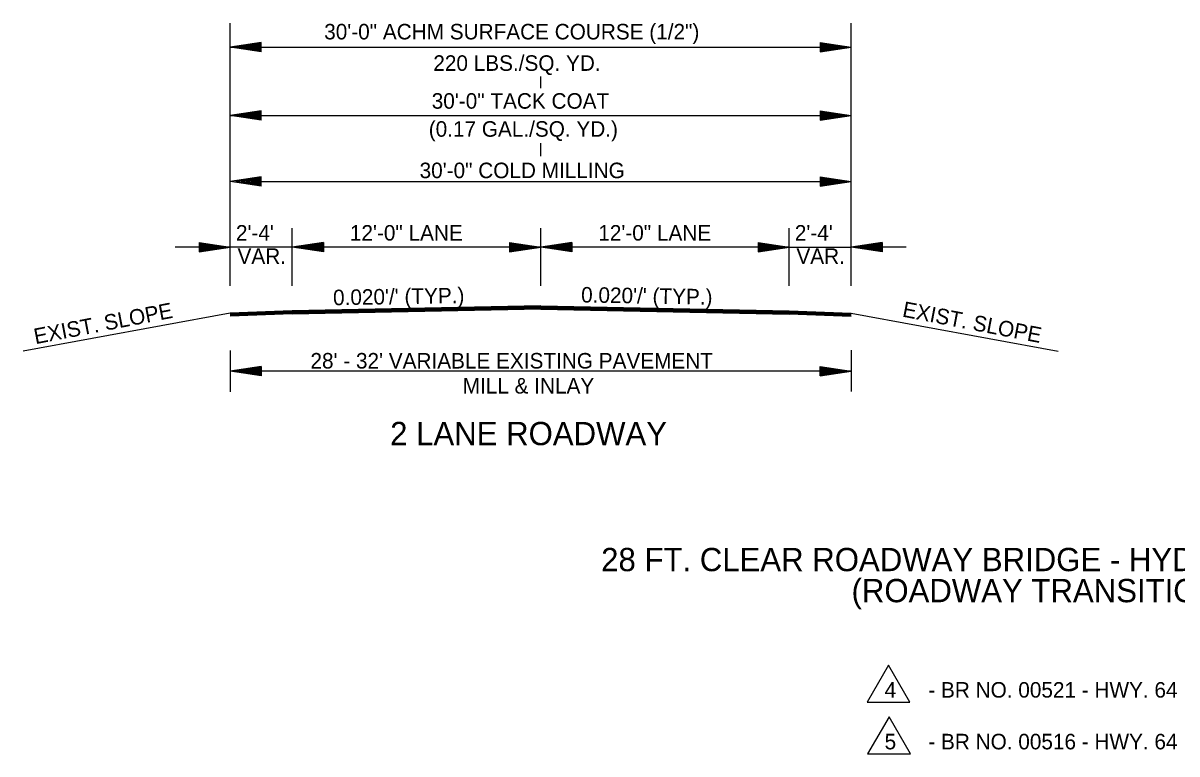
# Model space of a CAD drawing. Extents: x 549600 to 1930787, y -1955432 to 596640.
# Drawn here: x 551122 to 551679, y -1946099 to -1945746 of the extents above; entities that cross this region are included whole.
import ezdxf

# ---------------------------------------------------------------- set-up
doc = ezdxf.new("R2010")
doc.units = 0
doc.layers.add('R_Border', color=7, linetype='Continuous')
doc.layers.add('S_AREA_CALC', color=7, linetype='Continuous')

msp = doc.modelspace()

# ---------------------------------------------------------------- linework, layer by layer
at = {"layer": 'R_Border'}
for p, q in [((551529.77, -1946073.9), (551550.43, -1946073.9)), ((551529.96, -1946098.9), (551550.62, -1946098.9))]:
    msp.add_line(p, q, dxfattribs=at)
for points in [[(551550.43, -1946073.9), (551540.1, -1946056), (551529.77, -1946073.9)], [(551550.62, -1946098.9), (551540.29, -1946081), (551529.96, -1946098.9)]]:
    msp.add_lwpolyline(points, dxfattribs=at)
at = {"layer": 'S_AREA_CALC'}
for p, q in [((551222.02, -1945872.78), (551222.02, -1945745.75)), ((551522.02, -1945872.78), (551522.02, -1945745.75)), ((551237.02, -1945755.17), (551222.02, -1945757.42)), ((551237.02, -1945755.55), (551224.52, -1945757.42)), ((551237.02, -1945755.93), (551227.1, -1945757.42)), ((551237.02, -1945759.67), (551237.02, -1945755.17)), ((551507.02, -1945755.17), (551522.02, -1945757.42)), ((551507.02, -1945755.17), (551507.02, -1945759.67)), ((551507.02, -1945755.55), (551519.51, -1945757.42)), ((551507.02, -1945755.93), (551516.93, -1945757.42)), ((551222.02, -1945757.42), (551522.02, -1945757.42)), ((551237.02, -1945759.67), (551222.02, -1945757.42)), ((551237.02, -1945759.3), (551224.52, -1945757.42)), ((551237.02, -1945758.91), (551227.1, -1945757.42)), ((551237.02, -1945756.3), (551229.6, -1945757.42)), ((551237.02, -1945758.54), (551229.6, -1945757.42)), ((551237.02, -1945756.69), (551232.14, -1945757.42)), ((551237.02, -1945758.15), (551232.14, -1945757.42)), ((551237.02, -1945757.07), (551234.65, -1945757.42)), ((551237.02, -1945757.77), (551234.65, -1945757.42)), ((551507.02, -1945756.3), (551514.44, -1945757.42)), ((551507.02, -1945756.69), (551511.89, -1945757.42)), ((551507.02, -1945757.07), (551509.39, -1945757.42)), ((551507.02, -1945759.67), (551522.02, -1945757.42)), ((551507.02, -1945758.16), (551511.89, -1945757.42)), ((551507.02, -1945758.91), (551516.93, -1945757.42)), ((551507.02, -1945759.3), (551519.51, -1945757.42)), ((551507.02, -1945758.54), (551514.44, -1945757.42)), ((551507.02, -1945757.77), (551509.39, -1945757.42)), ((551372.02, -1945777.16), (551372.02, -1945771.63)), ((551237.02, -1945788.14), (551222.02, -1945790.39)), ((551237.02, -1945788.51), (551224.52, -1945790.39)), ((551237.02, -1945788.89), (551227.1, -1945790.39)), ((551237.02, -1945789.27), (551229.6, -1945790.39)), ((551237.02, -1945789.65), (551232.14, -1945790.39)), ((551237.02, -1945792.64), (551237.02, -1945788.14)), ((551507.02, -1945788.14), (551522.02, -1945790.39)), ((551507.02, -1945788.14), (551507.02, -1945792.64)), ((551507.02, -1945788.51), (551519.51, -1945790.39)), ((551507.02, -1945788.89), (551516.93, -1945790.39)), ((551507.02, -1945789.27), (551514.44, -1945790.39)), ((551507.02, -1945789.66), (551511.89, -1945790.39)), ((551222.02, -1945790.39), (551522.02, -1945790.39)), ((551237.02, -1945792.64), (551222.02, -1945790.39)), ((551237.02, -1945792.26), (551224.52, -1945790.39)), ((551237.02, -1945791.88), (551227.1, -1945790.39)), ((551237.02, -1945791.5), (551229.6, -1945790.39)), ((551237.02, -1945791.11), (551232.14, -1945790.39)), ((551237.02, -1945790.03), (551234.65, -1945790.39)), ((551237.02, -1945790.74), (551234.65, -1945790.39)), ((551507.02, -1945790.03), (551509.39, -1945790.39)), ((551507.02, -1945792.64), (551522.02, -1945790.39)), ((551507.02, -1945791.12), (551511.89, -1945790.39)), ((551507.02, -1945791.88), (551516.93, -1945790.39)), ((551507.02, -1945792.26), (551519.51, -1945790.39)), ((551507.02, -1945791.5), (551514.44, -1945790.39)), ((551507.02, -1945790.74), (551509.39, -1945790.39)), ((551372.02, -1945810.13), (551372.02, -1945803.71)), ((551237.02, -1945820.11), (551222.02, -1945822.36)), ((551237.02, -1945824.61), (551222.02, -1945822.36)), ((551237.02, -1945820.49), (551224.52, -1945822.36)), ((551237.02, -1945824.24), (551224.52, -1945822.36)), ((551237.02, -1945820.87), (551227.1, -1945822.36)), ((551237.02, -1945823.85), (551227.1, -1945822.36)), ((551237.02, -1945821.24), (551229.6, -1945822.36)), ((551237.02, -1945823.48), (551229.6, -1945822.36)), ((551232.02, -1945822.36), (551522.02, -1945822.36)), ((551237.02, -1945821.63), (551232.14, -1945822.36)), ((551237.02, -1945823.09), (551232.14, -1945822.36)), ((551237.02, -1945822.01), (551234.65, -1945822.36)), ((551237.02, -1945822.71), (551234.65, -1945822.36)), ((551237.02, -1945824.61), (551237.02, -1945820.11)), ((551507.02, -1945820.11), (551522.02, -1945822.36)), ((551507.02, -1945820.11), (551507.02, -1945824.61)), ((551507.02, -1945820.49), (551519.51, -1945822.36)), ((551507.02, -1945820.87), (551516.93, -1945822.36)), ((551507.02, -1945821.24), (551514.44, -1945822.36)), ((551507.02, -1945821.63), (551511.89, -1945822.36)), ((551507.02, -1945822.01), (551509.39, -1945822.36)), ((551507.02, -1945824.61), (551522.02, -1945822.36)), ((551507.02, -1945823.1), (551511.89, -1945822.36)), ((551507.02, -1945823.85), (551516.93, -1945822.36)), ((551507.02, -1945824.24), (551519.51, -1945822.36)), ((551507.02, -1945823.48), (551514.44, -1945822.36)), ((551507.02, -1945822.71), (551509.39, -1945822.36)), ((551252.02, -1945872.78), (551252.02, -1945844.83)), ((551372.02, -1945872.78), (551372.02, -1945844.83)), ((551492.02, -1945872.78), (551492.02, -1945844.83)), ((551222.02, -1945854.02), (551195.5, -1945854.02)), ((551207.02, -1945851.77), (551222.02, -1945854.02)), ((551207.02, -1945851.77), (551207.02, -1945856.27)), ((551207.02, -1945852.15), (551219.51, -1945854.02)), ((551207.02, -1945852.53), (551216.93, -1945854.02)), ((551207.02, -1945852.9), (551214.44, -1945854.02)), ((551207.02, -1945853.29), (551211.89, -1945854.02)), ((551207.02, -1945853.67), (551209.39, -1945854.02)), ((551207.02, -1945856.27), (551222.02, -1945854.02)), ((551207.02, -1945854.76), (551211.89, -1945854.02)), ((551207.02, -1945855.51), (551216.93, -1945854.02)), ((551207.02, -1945855.9), (551219.51, -1945854.02)), ((551207.02, -1945855.14), (551214.44, -1945854.02)), ((551207.02, -1945854.37), (551209.39, -1945854.02)), ((551252.02, -1945854.02), (551222.02, -1945854.02)), ((551267.02, -1945851.77), (551252.02, -1945854.02)), ((551372.02, -1945854.02), (551252.02, -1945854.02)), ((551267.02, -1945856.27), (551252.02, -1945854.02)), ((551267.02, -1945852.15), (551254.52, -1945854.02)), ((551267.02, -1945855.9), (551254.52, -1945854.02)), ((551267.02, -1945852.53), (551257.1, -1945854.02)), ((551267.02, -1945855.51), (551257.1, -1945854.02)), ((551267.02, -1945852.9), (551259.6, -1945854.02)), ((551267.02, -1945855.14), (551259.6, -1945854.02)), ((551267.02, -1945853.29), (551262.14, -1945854.02)), ((551267.02, -1945854.76), (551262.14, -1945854.02)), ((551267.02, -1945853.67), (551264.65, -1945854.02)), ((551267.02, -1945854.37), (551264.65, -1945854.02)), ((551267.02, -1945851.77), (551267.02, -1945856.27)), ((551357.02, -1945851.77), (551372.02, -1945854.02)), ((551357.02, -1945851.77), (551357.02, -1945856.27)), ((551357.02, -1945852.15), (551369.51, -1945854.02)), ((551357.02, -1945852.53), (551366.93, -1945854.02)), ((551357.02, -1945852.9), (551364.44, -1945854.02)), ((551357.02, -1945853.29), (551361.89, -1945854.02)), ((551357.02, -1945853.67), (551359.39, -1945854.02)), ((551357.02, -1945856.27), (551372.02, -1945854.02)), ((551357.02, -1945854.76), (551361.89, -1945854.02)), ((551357.02, -1945855.51), (551366.93, -1945854.02)), ((551357.02, -1945855.9), (551369.51, -1945854.02)), ((551357.02, -1945855.14), (551364.44, -1945854.02)), ((551357.02, -1945854.37), (551359.39, -1945854.02)), ((551387.02, -1945851.77), (551372.02, -1945854.02)), ((551492.02, -1945854.02), (551372.02, -1945854.02)), ((551387.02, -1945856.27), (551372.02, -1945854.02)), ((551387.02, -1945852.15), (551374.52, -1945854.02)), ((551387.02, -1945855.9), (551374.52, -1945854.02)), ((551387.02, -1945852.53), (551377.1, -1945854.02)), ((551387.02, -1945855.51), (551377.1, -1945854.02)), ((551387.02, -1945852.9), (551379.6, -1945854.02)), ((551387.02, -1945855.14), (551379.6, -1945854.02)), ((551387.02, -1945853.29), (551382.14, -1945854.02)), ((551387.02, -1945854.76), (551382.14, -1945854.02)), ((551387.02, -1945853.67), (551384.65, -1945854.02)), ((551387.02, -1945854.37), (551384.65, -1945854.02)), ((551387.02, -1945851.77), (551387.02, -1945856.27)), ((551477.02, -1945851.77), (551492.02, -1945854.02)), ((551477.02, -1945851.77), (551477.02, -1945856.27)), ((551477.02, -1945852.15), (551489.51, -1945854.02)), ((551477.02, -1945852.53), (551486.93, -1945854.02)), ((551477.02, -1945852.9), (551484.44, -1945854.02)), ((551477.02, -1945853.29), (551481.89, -1945854.02)), ((551477.02, -1945853.67), (551479.39, -1945854.02)), ((551477.02, -1945856.27), (551492.02, -1945854.02)), ((551477.02, -1945854.76), (551481.89, -1945854.02)), ((551477.02, -1945855.51), (551486.93, -1945854.02)), ((551477.02, -1945855.9), (551489.51, -1945854.02)), ((551477.02, -1945855.14), (551484.44, -1945854.02)), ((551477.02, -1945854.37), (551479.39, -1945854.02)), ((551492.02, -1945854.02), (551522.02, -1945854.02)), ((551537.02, -1945851.77), (551522.02, -1945854.02)), ((551537.02, -1945856.27), (551522.02, -1945854.02)), ((551548.54, -1945854.02), (551522.02, -1945854.02)), ((551537.02, -1945852.15), (551524.52, -1945854.02)), ((551537.02, -1945855.9), (551524.52, -1945854.02)), ((551537.02, -1945852.53), (551527.1, -1945854.02)), ((551537.02, -1945855.51), (551527.1, -1945854.02)), ((551537.02, -1945852.9), (551529.6, -1945854.02)), ((551537.02, -1945855.14), (551529.6, -1945854.02)), ((551537.02, -1945853.29), (551532.14, -1945854.02)), ((551537.02, -1945854.76), (551532.14, -1945854.02)), ((551537.02, -1945853.67), (551534.65, -1945854.02)), ((551537.02, -1945854.37), (551534.65, -1945854.02)), ((551537.02, -1945851.77), (551537.02, -1945856.27)), ((551372.02, -1945882.33), (551252.02, -1945884.73)), ((551372.02, -1945882.63), (551252.02, -1945885.03)), ((551372.02, -1945882.93), (551252.02, -1945885.33)), ((551372.02, -1945883.23), (551252.02, -1945885.63)), ((551372.02, -1945883.53), (551252.02, -1945885.93)), ((551372.02, -1945883.83), (551252.02, -1945886.23)), ((551372.02, -1945884), (551252.02, -1945886.4)), ((551372.02, -1945882.33), (551492.02, -1945884.73)), ((551372.02, -1945882.63), (551492.02, -1945885.03)), ((551372.02, -1945882.93), (551492.02, -1945885.33)), ((551372.02, -1945883.23), (551492.02, -1945885.63)), ((551372.02, -1945883.53), (551492.02, -1945885.93)), ((551372.02, -1945883.83), (551492.02, -1945886.23)), ((551372.02, -1945884), (551492.02, -1945886.4)), ((551222.02, -1945885.93), (551121.95, -1945904.31)), ((551252.02, -1945884.73), (551222.02, -1945885.93)), ((551252.02, -1945885.03), (551222.02, -1945886.23)), ((551252.02, -1945885.33), (551222.02, -1945886.53)), ((551252.02, -1945885.63), (551222.02, -1945886.83)), ((551252.02, -1945885.93), (551222.02, -1945887.13)), ((551252.02, -1945886.23), (551222.02, -1945887.43)), ((551492.02, -1945884.73), (551522.02, -1945885.93)), ((551492.02, -1945885.03), (551522.02, -1945886.23)), ((551492.02, -1945885.33), (551522.02, -1945886.53)), ((551492.02, -1945885.63), (551522.02, -1945886.83)), ((551492.02, -1945885.93), (551522.02, -1945887.13)), ((551492.02, -1945886.23), (551522.02, -1945887.43)), ((551522.02, -1945885.93), (551622.09, -1945904.31)), ((551222.02, -1945903.99), (551222.02, -1945923.99)), ((551522.02, -1945903.74), (551522.02, -1945923.74)), ((551237.02, -1945911.74), (551222.02, -1945913.99)), ((551237.02, -1945912.11), (551224.52, -1945913.99)), ((551237.02, -1945911.74), (551237.02, -1945916.24)), ((551507.02, -1945911.74), (551522.02, -1945913.99)), ((551507.02, -1945916.24), (551507.02, -1945911.74)), ((551507.02, -1945912.11), (551519.51, -1945913.99)), ((551237.02, -1945916.24), (551222.02, -1945913.99)), ((551522.02, -1945913.99), (551222.02, -1945913.99)), ((551237.02, -1945915.86), (551224.52, -1945913.99)), ((551237.02, -1945912.5), (551227.1, -1945913.99)), ((551237.02, -1945915.48), (551227.1, -1945913.99)), ((551237.02, -1945912.87), (551229.6, -1945913.99)), ((551237.02, -1945915.11), (551229.6, -1945913.99)), ((551237.02, -1945913.26), (551232.14, -1945913.99)), ((551237.02, -1945914.72), (551232.14, -1945913.99)), ((551237.02, -1945913.64), (551234.65, -1945913.99)), ((551237.02, -1945914.34), (551234.65, -1945913.99)), ((551507.02, -1945912.5), (551516.93, -1945913.99)), ((551507.02, -1945912.87), (551514.44, -1945913.99)), ((551507.02, -1945913.25), (551511.89, -1945913.99)), ((551507.02, -1945913.64), (551509.39, -1945913.99)), ((551507.02, -1945916.24), (551522.02, -1945913.99)), ((551507.02, -1945914.72), (551511.89, -1945913.99)), ((551507.02, -1945915.48), (551516.93, -1945913.99)), ((551507.02, -1945915.86), (551519.51, -1945913.99)), ((551507.02, -1945915.11), (551514.44, -1945913.99)), ((551507.02, -1945914.34), (551509.39, -1945913.99))]:
    msp.add_line(p, q, dxfattribs=at)

# ---------------------------------------------------------------- texts
at = {"layer": 'R_Border'}
for s, height, p in [('28 FT. CLEAR ROADWAY BRIDGE - HYDRODEMOLITION', 11.25, (551401.23, -1946010.6)), ('(ROADWAY TRANSITIONS)', 11.25, (551522.18, -1946025.6)), ('4', 7.5, (551538.16, -1946071.69)), ('- BR NO. 00521 - HWY. 64', 7.5, (551559.29, -1946071.69)), ('5', 7.5, (551538.16, -1946096.69)), ('- BR NO. 00516 - HWY. 64', 7.5, (551559.29, -1946096.69))]:
    msp.add_text(s, height=height, dxfattribs=at).set_placement(p)
at = {"layer": 'S_AREA_CALC'}
for s, height, p in [('30\'-0" ACHM SURFACE COURSE (1/2")', 7.5, (551267.43, -1945753.65)), ('220 LBS./SQ. YD. ', 7.5, (551320.14, -1945768.83)), ('30\'-0" TACK COAT', 7.5, (551319.37, -1945787.12)), ('(0.17 GAL./SQ. YD.)', 7.5, (551317.93, -1945800.67)), ('30\'-0" COLD MILLING ', 7.5, (551313.52, -1945820.69)), ("2'-4'", 7.5, (551224.79, -1945850.85)), ('12\'-0" LANE', 7.5, (551279.84, -1945850.85)), ('12\'-0" LANE', 7.5, (551399.84, -1945850.85)), ("2'-4'", 7.5, (551494.79, -1945850.85)), ('VAR.', 7.5, (551225.56, -1945862.1)), ('VAR.', 7.5, (551495.56, -1945862.1)), ("28' - 32' VARIABLE EXISTING PAVEMENT", 7.5, (551260.79, -1945912.67)), ('MILL & INLAY', 7.5, (551334.34, -1945924.76)), ('2 LANE ROADWAY', 11.25, (551299.29, -1945949.71))]:
    msp.add_text(s, height=height, dxfattribs=at).set_placement(p)
for s, rotation, p in [("0.020'/' (TYP.)", 0.9719, (551271.76, -1945882.12)), ("0.020'/' (TYP.)", 359.0281, (551391.5, -1945880.75)), ('EXIST. SLOPE', 10.8829, (551127.93, -1945900.93)), ('EXIST. SLOPE', 349.1171, (551546.4, -1945887.53))]:
    msp.add_text(s, height=7.5, rotation=rotation, dxfattribs=at).set_placement(p)

doc.saveas('drawing.dxf')
